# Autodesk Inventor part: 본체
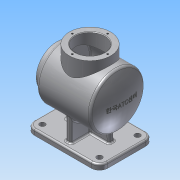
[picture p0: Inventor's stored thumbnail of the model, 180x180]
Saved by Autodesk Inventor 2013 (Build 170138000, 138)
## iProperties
Created: 2016-09
Part Number: 본체
Material: 알루미늄 6061
Document SubType Name: Modeling
Designer: Administrator
Density: 2.71 g/cm^3
Mass: 970.206 g
Surface Area: 1287.5 cm^2
Volume: 358.009 cm^3
Author: Administrator
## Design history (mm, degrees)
sketch "스케치1"
  geometry: L1 (-67.5, 50)-(67.5, 50); L2 (67.5, 50)-(67.5, -50); L3 (67.5, -50)-(-67.5, -50); L4 (-67.5, -50)-(-67.5, 50); C1 r 5 at (-52.5, -35); C2 r 5 at (52.5, -35); C3 r 5 at (52.5, 35); C4 r 5 at (-52.5, 35); 5 further points
  constraints: 8 end point, 4 centre point, 4 horizontal alignment, 4 midpoint, 4 vertical alignment, 3 equal radius, 2 parallel, 1 horizontal, 1 perpendicular
  dimensions: "d0" = 135 distance of L1.start L1.end; "d2" = 100 distance of L1.end L2.end; "d3" = 10 diameter of C4; "d4" = 15 distance from line of L4 C4.centre; "d5" = 15 distance from line of L1 C4.centre; "d6" = 15 distance from line of L3 C1.centre; "d7" = 15 distance from line of L2 C2.centre
extrude "돌출1" new body sketch "스케치1" distance "d8" = 10; taper "d9" = 0 deg
sketch "스케치2"
  geometry: L1 (-61, 82)-(61, 82); L2 (-67.5, 0)-(67.5, 0) reference; L3 (-61, 82)-(-61, 120); L4 (-61, 120)-(-49, 120); L5 (-49, 120)-(-49, 132); L6 (-49, 132)-(49.562, 132); A1 r 115 centre (-54, 82) between (61, 82) and (49.562, 132); 3 further points
  constraints: 10 end point, 2 parallel, 2 perpendicular, 2 point on circle, 1 centre point, 1 coincident, 1 horizontal, 1 midpoint, 1 point on line, 1 vertical alignment
  dimensions: "d10" = 122 distance of L1.end L1.start; "d13" = 82 vertical distance of L2.start L1.start; "d14" = 7 distance of L1.start point (-54, 82); "d15" = 76 diameter of L4 L1; "d16" = 100 diameter of L6 L1; "d17" = 12 distance of L3.end L4.end
revolve "회전1" sketch "스케치2" stored, may be unused: angle "d18" = 90 deg
node "작업 평면1"
sketch "스케치3"
  geometry: C1 r 38 at (0, 0); 1 further point
  constraints: 1 centre point, 1 coincident
  dimensions: "d20" = 76 diameter of C1
extrude "돌출2" join sketch "스케치3" distance "d21" = 65; taper "d22" = 0 deg
sketch "스케치4"
  geometry: L1 (-67.5, 0)-(67.5, 0) reference; L2 (67.5, 10)-(-67.5, 10) reference; L3 (-40, 10)-(-36.181, 53.649); L4 (-36.181, 53.649)-(36.181, 53.649); L5 (36.181, 53.649)-(40, 10); 1 further point
  constraints: 6 end point, 2 point on line, 1 parallel
  dimensions: "d23" = 40 horizontal distance of L3.start point (0, 0); "d24" = 40 horizontal distance of point (0, 0) L5.end; "d25" = 95 deg angle of L2 L3; "d26" = 95 deg angle of L2 L5; "d27" = 43.64903 distance between parallel lines of L2 L4
extrude "돌출3" join sketch "스케치4" stored distance "d28" = 10; taper "d29" = 0 deg
sketch "스케치5"
  geometry: L1 (50, 10)-(-50, 10) reference; L2 (-50, 0)-(50, 0) reference; L3 (-40, 10)-(-40, 57.422); L4 (-40, 57.422)-(40, 57.422); L5 (40, 57.422)-(40, 10); 1 further point
  constraints: 6 end point, 2 perpendicular, 2 point on line, 1 parallel
  dimensions: "d30" = 40 horizontal distance of L3.start point (0, 0); "d31" = 40 horizontal distance of point (0, 0) L5.end; "d32" = 47.42184 distance between parallel lines of L1 L4
extrude "돌출4" join sketch "스케치5" stored distance "d33" = 10; taper "d34" = 0 deg
node "작업 평면2"
node "작업 평면3"
sketch "스케치7"
  geometry: 2 further points
  constraints: 1 vertical alignment, 1 other
  dimensions: "d37" = 82 distance of point (0, 0) point (0, 82)
feature "엠보싱1" sketch "스케치7" dims "d0" = 135, "d2" = 100, "d3" = 10, "d4" = 15, "d5" = 15, "d6" = 15, "d7" = 15, "d38" = 0.5, "d39" = 0
sketch "스케치8"
  geometry: L1 (-61, 82)-(61, 82); L2 (-67.5, 0)-(67.5, 0) reference; L3 (-61, 82)-(-61, 109); L4 (-61, 109)-(-46, 109); L5 (-46, 109)-(-46, 129); L6 (-46, 129)-(47.661, 129); L7 (-49, 132)-(49.562, 132) reference; A1 r 115 centre (-54, 82) between (49.562, 32) and (49.562, 132) reference; A2 r 112 centre (-54, 82) between (58, 82) and (47.661, 129); 3 further points
  constraints: 10 end point, 4 perpendicular, 2 point on circle, 2 point on line, 1 centre point, 1 coincident, 1 horizontal, 1 midpoint, 1 vertical alignment
  dimensions: "d40" = 122 distance of L1.start L1.end; "d42" = 82 distance between parallel lines of L2 L1; "d45" = 54 diameter of L4 L1; "d46" = 15 distance of L3.end L4.end; "d47" = 7 distance of L1.start point (-54, 82); "d49" = 224 diameter of A2; "d50" = 94 diameter of L6 L1
revolve "회전2" sketch "스케치8" stored, may be unused: angle "d51" = 90 deg
hole "구멍1" diameter "d54" = 54; stored, may be unused: countersink angle "d58" = 90 deg, drill point angle "d60" = 0 deg; dims "d52" = 10, "d53" = 10, "d55" = 6, "d56" = 4, "d57" = 2, "d59" = 40
sketch "스케치9"
  geometry: 2 further points
  constraints: 1 horizontal alignment
  dimensions: "d61" = 114.5 distance of point (82, 0) point (-32.5, 0)
hole "구멍2" sketch "스케치9" at (-32.5, 0) diameter "d62" = 3.242; stored, may be unused: countersink angle "d66" = 90 deg, drill point angle "d68" = 118 deg; dims "d63" = 8, "d64" = 4, "d65" = 2, "d67" = 10
sketch "스케치10"
  geometry: L1 (61, 38)-(61, -38) reference; 2 further points
  constraints: 1 vertical alignment
  dimensions: "d72" = 32.5 distance of point (0, 0) point (0, 32.5)
hole "구멍3" sketch "스케치10" at (0, 32.5) diameter "d73" = 3.242; stored, may be unused: countersink angle "d77" = 90 deg, drill point angle "d79" = 118 deg; dims "d74" = 8, "d75" = 4, "d76" = 2, "d78" = 10
fillet "모깎기1" dims "d83" = 15
fillet "모깎기2" dims "d84" = 5
fillet "모깎기3" dims "d85" = 5
fillet "모깎기4" dims "d86" = 2
fillet "모깎기5" dims "d87" = 2
fillet "모깎기6" dims "d88" = 3
fillet "모깎기7" dims "d89" = 3
fillet "모깎기8" dims "d90" = 3
fillet "모깎기9" dims "d91" = 3
fillet "모깎기10" dims "d92" = 3
chamfer "모따기1" distance "d93" = 1; stored, may be unused: second distance "d94" = 2, angle "d95" = 45 deg
chamfer "모따기2" distance "d96" = 1; stored, may be unused: second distance "d97" = 2, angle "d98" = 45 deg
node "솔리드1"
pattern_circular "원형 패턴1" dims angle "d70" = 360 deg
pattern_circular "원형 패턴2" dims angle "d81" = 360 deg
other parameters: "d19" = 82, "d36" = -48
